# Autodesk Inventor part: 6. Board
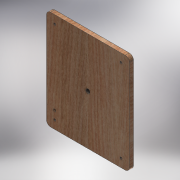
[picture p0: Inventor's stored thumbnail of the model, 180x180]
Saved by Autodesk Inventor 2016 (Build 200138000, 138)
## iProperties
Created: 2016-01
Part Number: 6. Board
Material: Generic
Document SubType Name: Modeling
Designer: Black Falcon
Density: 1 g/cm^3
Appearance: Birch - Natural Polished
Author: Black Falcon
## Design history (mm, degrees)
sketch "Sketch1"
  geometry: L1 (-127, -152.4)-(127, -152.4); L2 (127, -152.4)-(127, 152.4); L3 (127, 152.4)-(-127, 152.4); L4 (-127, 152.4)-(-127, -152.4); L5 (-127, -152.4)-(127, 152.4); L6 (127, -152.4)-(-127, 152.4); 1 further point
  constraints: 12 end point, 2 midpoint, 2 parallel, 1 horizontal, 1 perpendicular
  dimensions: "d0" = 254 distance of L2.end L3.end; "d1" = 304.8 distance of L1.end L2.end
extrude "Extrusion1" new body sketch "Sketch1" distance "d2" = 12.7; taper "d3" = 0 deg
sketch "Sketch2"
  geometry: C1 r 6.35 at (0, 0); 1 further point
  constraints: 1 centre point, 1 coincident
  dimensions: "d4" = 12.7 diameter of C1
extrude "Extrusion2" cut sketch "Sketch2" stored distance "d5" = 25.4; taper "d6" = 0 deg
fillet "Fillet1" dims "d7" = 12.7
sketch "Sketch3"
  geometry: L1 (0, 0)-(-194.677, 0); L2 (0, 0)-(0, 119.574); C1 r 3.2 at (20.32, 76.2) reference; C2 r 3.2 at (-20.32, 76.2) reference; C3 r 3.2 at (-20.32, -76.2) reference; C4 r 3.2 at (20.32, -76.2) reference; C5 r 6.35 at (0, 0) reference; 4 further points
  constraints: 4 end point, 3 symmetric about line, 1 horizontal, 1 vertical
  dimensions: "d19" = 101.6 distance from line of L2 point (-101.6, 127); "d20" = 127 vertical distance of L1.start point (-101.6, 127)
hole "Hole1" sketch "Sketch3" at (-101.6, 127), (101.6, 127), (-101.6, -127), (101.6, -127) diameter "d8" = 6.4008; stored, may be unused: countersink angle "d12" = 82 deg, drill point angle "d14" = 118 deg; dims "d9" = 15.875, "d10" = 9.525, "d11" = 6.35, "d13" = 22.9362
thread "Thread1" dims "d15" = 25.4, "d16" = 0
sketch "Sketch4"
  geometry: C1 r 3.81 at (101.6, -101.6) reference; 1 further point
extrude "Extrusion3" cut sketch "Sketch4" stored distance "d17" = 25.4; taper "d18" = 0 deg
sketch "Sketch5"
  geometry: L1 (-107.108, 112.143)-(115.804, 112.143); L2 (115.804, 112.143)-(115.804, 62.251); L3 (115.804, 62.251)-(-107.108, 62.251); L4 (-107.108, 62.251)-(-107.108, 112.143); 1 further point
  constraints: 2 other
emboss "Emboss1" sketch "Sketch5" dims "d0" = 254, "d1" = 304.8, "d21" = 1.27, "d22" = 0
fillet "Fillet2" dims "d23" = 0.508
fillet "Fillet3" dims "d24" = 0.254
fillet "Fillet4" dims "d25" = 0.508
fillet "Fillet5" dims "d26" = 0.254
body "Solid1"
node "Reference1"
node "Reference2"
node "Reference3"
node "Reference4"
node "Reference5"
